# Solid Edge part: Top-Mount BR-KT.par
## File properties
Author: nakano
Template: iso metric part.par
Last saved by: nakano
Revision: 4
Application: Solid Edge
Density: 711.280 kg/m^3
Accuracy: 0.990
Username: nakano
Material: AL5D plastic
Face Style: Black (dull)
Fill Style: Normal
Virtual Style: Normal
Grouping: Non-metals
LibraryName: Materials-GOST
Coef. of Thermal Exp: 0.0
Thermal Conductivity: 0.0
Specific Heat: 0.0
Modulus of Elasticity: 0.0
Poisson's Ratio: 0.33
Yield Stress: 0.0
Ultimate Stress: 0.0
Elongation: 0.0
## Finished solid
Body 1: solid body, 69 faces, 176 edges, 96 vertices.
  Faces by surface: plane 53, cylinder 16
  Edges by curve: line 144, circle 32
Bounding box of the edges (mm): 93.980 x 9.398 x 93.980, from (-46.99, 0, -46.99) to (46.99, 9.398, 46.99).
Cylindrical faces by radius (mm): R1.1811 x1, R1.1938 x8, R1.5875 x4, R4.445 x1, R34.29 x1, R46.99 x1
Planar faces by outward normal: +x 2, +y 4, +z 2, -x 2, -y 1, -z 2, oblique 40
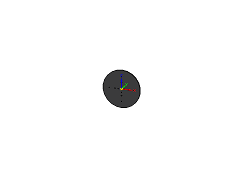
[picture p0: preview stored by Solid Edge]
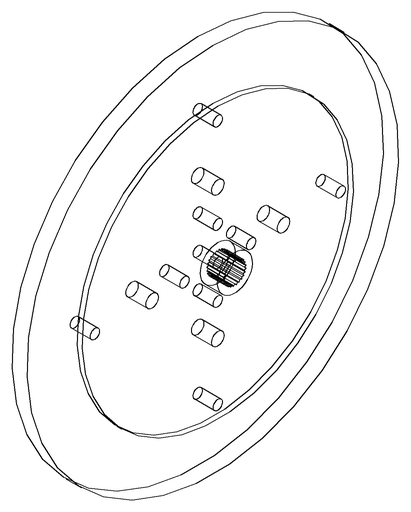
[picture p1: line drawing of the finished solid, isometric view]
